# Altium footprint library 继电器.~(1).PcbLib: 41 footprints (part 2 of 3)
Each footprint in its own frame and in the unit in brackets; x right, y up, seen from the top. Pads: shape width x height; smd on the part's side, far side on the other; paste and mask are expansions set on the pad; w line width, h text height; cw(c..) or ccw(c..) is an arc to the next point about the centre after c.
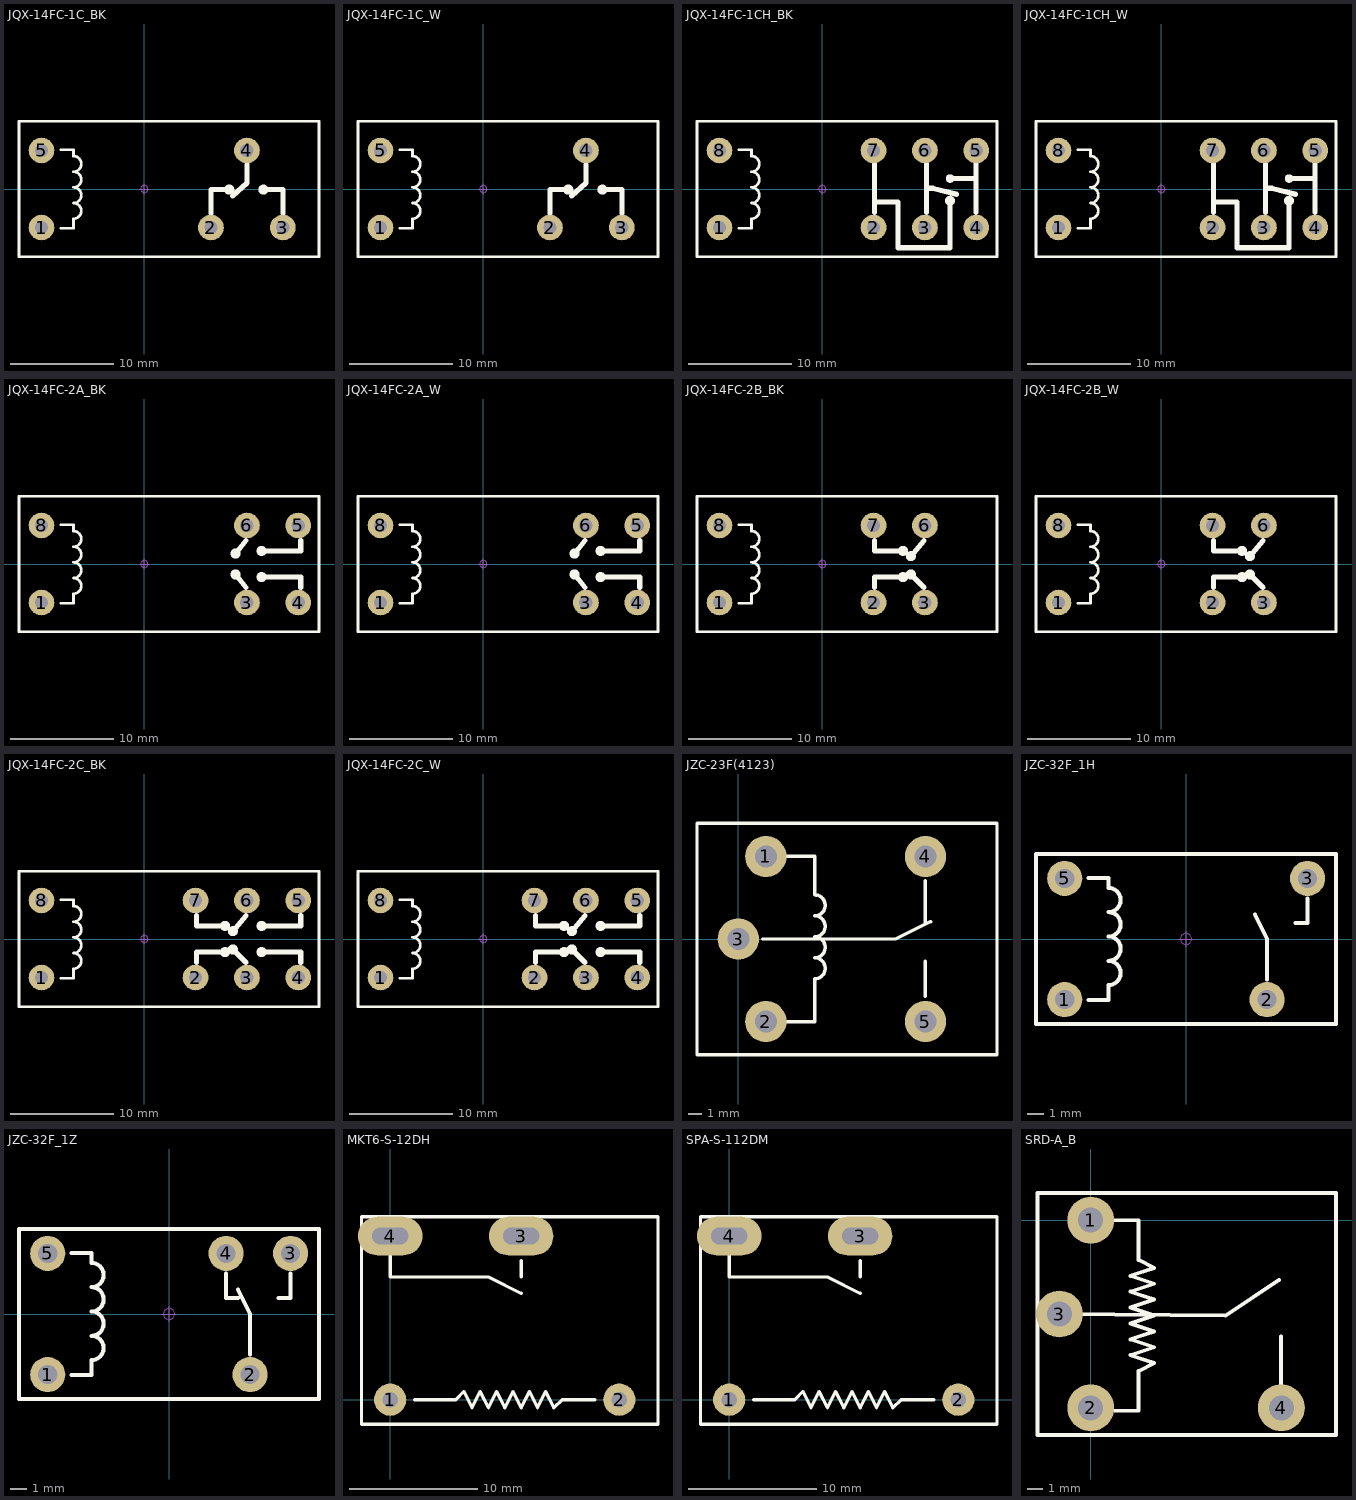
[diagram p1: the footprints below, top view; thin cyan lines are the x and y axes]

## JQX-14FC-1C_BK [mm] "单刀双投，长：29mm，宽：13mm，高：26mm"
pads (5):
  round 2.5 hole 1.3: 1(-10,-3.75) 2(6.5,-3.75) 3(13.5,-3.75) 4(10,3.75) 5(-10,3.75)
Top Overlay:
  circle w0.254: c11.595,-0.06 r0.359
  circle w0.254: c8.278,-0.06 r0.37
  lines w0.25: -12.192,-6.604 17.018,-6.604 17.018,6.604 -12.065,6.604 -12.192,6.604 -12.192,-6.604
  lines w0.254: -8.128,-3.81 -6.89,-3.81 -6.89,-2.89 ccw(c-6.89,-2.128) -6.89,-1.366 ccw(c-6.89,-0.604) -6.89,0.158 ccw(c-6.89,0.92) -6.89,1.682 ccw(c-6.89,2.444) -6.89,3.206 -6.89,3.81 -8.128,3.81
  lines w0.508: 6.5,-2.353 6.5,-0.06 8.278,-0.06 ; 8.603,-0.695 10,0.575 10,2.353 ; 11.595,-0.06 13.5,-0.06 13.5,-2.353
Mechanical 15:
  circle w0.05: c0,0 r0.35
  lines w0.05: -0.5,0 0.5,0 ; 0,-0.5 0,0.5
3D body: height 26.35, standoff -3.65, extent -12.1,-6.5 16.9,6.5

## JQX-14FC-1C_W [mm] "单刀双投，长：29mm，宽：13mm，高：26mm"
pads (5):
  round 2.5 hole 1.3: 1(-10,-3.75) 2(6.5,-3.75) 3(13.5,-3.75) 4(10,3.75) 5(-10,3.75)
Top Overlay:
  circle w0.254: c8.278,-0.06 r0.37
  circle w0.254: c11.595,-0.06 r0.359
  lines w0.25: -12.192,-6.604 -12.192,6.604 -12.065,6.604 17.018,6.604 17.018,-6.604 -12.192,-6.604
  lines w0.254: -8.128,-3.81 -6.89,-3.81 -6.89,-2.89 ccw(c-6.89,-2.128) -6.89,-1.366 ccw(c-6.89,-0.604) -6.89,0.158 ccw(c-6.89,0.92) -6.89,1.682 ccw(c-6.89,2.444) -6.89,3.206 -6.89,3.81 -8.128,3.81
  lines w0.508: 6.5,-2.353 6.5,-0.06 8.278,-0.06 ; 8.603,-0.695 10,0.575 10,2.353 ; 11.595,-0.06 13.5,-0.06 13.5,-2.353
Mechanical 15:
  circle w0.05: c0,0 r0.35
  lines w0.05: -0.5,0 0.5,0 ; 0,-0.5 0,0.5
3D body: height 26.35, standoff -3.65, extent -12.1,-6.5 16.9,6.5

## JQX-14FC-1CH_BK [mm] "单刀双投，长：29mm，宽：13mm，高：26mm"
pads (8):
  round 2.5 hole 1.3: 1(-10,-3.75) 2(5,-3.75) 3(10,-3.75) 4(15,-3.75) 5(15,3.75) 6(10,3.75) 7(5,3.75) 8(-10,3.75)
Top Overlay:
  circle w0.254: c12.446,-1.143 r0.359
  circle w0.254: c12.446,1.016 r0.284
  lines w0.25: -12.192,-6.604 -12.192,6.604 -12.065,6.604 17.018,6.604 17.018,-6.604 -12.192,-6.604
  lines w0.254: -8.128,-3.81 -6.89,-3.81 -6.89,-2.89 ccw(c-6.89,-2.128) -6.89,-1.366 ccw(c-6.89,-0.604) -6.89,0.158 ccw(c-6.89,0.92) -6.89,1.682 ccw(c-6.89,2.444) -6.89,3.206 -6.89,3.81 -8.128,3.81
  lines w0.508: 5.08,-2.286 5.08,2.413 ; 5.08,-1.27 7.366,-1.27 7.366,-5.715 12.446,-5.715 12.446,-2.413 12.446,-1.143 ; 10.16,-2.286 10.16,2.413 ; 10.16,0.064 10.795,0.064 13.081,-0.508 ; 12.446,1.016 14.986,1.016 ; 14.986,-2.286 14.986,2.413
Mechanical 15:
  circle w0.05: c0,0 r0.35
  lines w0.05: -0.5,0 0.5,0 ; 0,-0.5 0,0.5
3D body: height 26.35, standoff -3.65, extent -12.1,-6.5 16.9,6.5

## JQX-14FC-1CH_W [mm] "单刀双投，长：29mm，宽：13mm，高：26mm"
pads (8):
  round 2.5 hole 1.3: 1(-10,-3.75) 2(5,-3.75) 3(10,-3.75) 4(15,-3.75) 5(15,3.75) 6(10,3.75) 7(5,3.75) 8(-10,3.75)
Top Overlay:
  circle w0.254: c12.446,-1.143 r0.359
  circle w0.254: c12.446,1.016 r0.284
  lines w0.25: -12.192,-6.604 -12.192,6.604 -12.065,6.604 17.018,6.604 17.018,-6.604 -12.192,-6.604
  lines w0.254: -8.128,-3.81 -6.89,-3.81 -6.89,-2.89 ccw(c-6.89,-2.128) -6.89,-1.366 ccw(c-6.89,-0.604) -6.89,0.158 ccw(c-6.89,0.92) -6.89,1.682 ccw(c-6.89,2.444) -6.89,3.206 -6.89,3.81 -8.128,3.81
  lines w0.508: 5.08,-2.286 5.08,2.413 ; 5.08,-1.27 7.366,-1.27 7.366,-5.715 12.446,-5.715 12.446,-2.413 12.446,-1.143 ; 10.16,-2.286 10.16,2.413 ; 10.16,0.064 10.795,0.064 13.081,-0.508 ; 12.446,1.016 14.986,1.016 ; 14.986,-2.286 14.986,2.413
Mechanical 15:
  circle w0.05: c0,0 r0.35
  lines w0.05: -0.5,0 0.5,0 ; 0,-0.5 0,0.5
3D body: height 26.35, standoff -3.65, extent -12.1,-6.5 16.9,6.5

## JQX-14FC-2A_BK [mm] "双刀常开，长：29mm，宽：13mm，高：26mm"
pads (6):
  round 2.5 hole 1.3: 1(-10,-3.75) 3(10,-3.75) 4(15,-3.75) 5(15,3.75) 6(10,3.75) 8(-10,3.75)
Top Overlay:
  circle w0.254: c8.89,-1.016 r0.359
  circle w0.254: c8.89,1.016 r0.359
  circle w0.254: c11.43,-1.27 r0.359
  circle w0.254: c11.43,1.27 r0.359
  lines w0.25: -12.192,-6.604 -12.192,6.604 -12.065,6.604 17.018,6.604 17.018,-6.604 -12.192,-6.604
  lines w0.254: -8.128,-3.81 -6.89,-3.81 -6.89,-2.89 ccw(c-6.89,-2.128) -6.89,-1.366 ccw(c-6.89,-0.604) -6.89,0.158 ccw(c-6.89,0.92) -6.89,1.682 ccw(c-6.89,2.444) -6.89,3.206 -6.89,3.81 -8.128,3.81
  lines w0.508: 8.89,-1.016 9.906,-2.286 ; 8.89,1.016 9.906,2.286 ; 11.43,-1.27 15.24,-1.27 15.24,-2.286 ; 11.43,1.27 15.24,1.27 15.24,2.286
Mechanical 15:
  circle w0.05: c0,0 r0.35
  lines w0.05: -0.5,0 0.5,0 ; 0,-0.5 0,0.5
3D body: height 26.35, standoff -3.65, extent -12.1,-6.5 16.9,6.5

## JQX-14FC-2A_W [mm] "双刀常开，长：29mm，宽：13mm，高：26mm"
pads (6):
  round 2.5 hole 1.3: 1(-10,-3.75) 3(10,-3.75) 4(15,-3.75) 5(15,3.75) 6(10,3.75) 8(-10,3.75)
Top Overlay:
  circle w0.254: c8.89,-1.016 r0.359
  circle w0.254: c8.89,1.016 r0.359
  circle w0.254: c11.43,-1.27 r0.359
  circle w0.254: c11.43,1.27 r0.359
  lines w0.25: -12.192,-6.604 -12.192,6.604 -12.065,6.604 17.018,6.604 17.018,-6.604 -12.192,-6.604
  lines w0.254: -8.128,-3.81 -6.89,-3.81 -6.89,-2.89 ccw(c-6.89,-2.128) -6.89,-1.366 ccw(c-6.89,-0.604) -6.89,0.158 ccw(c-6.89,0.92) -6.89,1.682 ccw(c-6.89,2.444) -6.89,3.206 -6.89,3.81 -8.128,3.81
  lines w0.508: 8.89,-1.016 9.906,-2.286 ; 8.89,1.016 9.906,2.286 ; 11.43,-1.27 15.24,-1.27 15.24,-2.286 ; 11.43,1.27 15.24,1.27 15.24,2.286
Mechanical 15:
  circle w0.05: c0,0 r0.35
  lines w0.05: -0.5,0 0.5,0 ; 0,-0.5 0,0.5
3D body: height 26.35, standoff -3.65, extent -12.1,-6.5 16.9,6.5

## JQX-14FC-2B_BK [mm] "双刀常闭，长：29mm，宽：13mm，高：26mm"
pads (6):
  round 2.5 hole 1.3: 1(-10,-3.75) 2(5,-3.75) 3(10,-3.75) 6(10,3.75) 7(5,3.75) 8(-10,3.75)
Top Overlay:
  circle w0.254: c8.636,-1.016 r0.359
  circle w0.254: c8.636,0.762 r0.359
  circle w0.254: c7.874,-1.27 r0.359
  circle w0.254: c7.874,1.27 r0.359
  lines w0.25: -12.192,-6.604 -12.192,6.604 -12.065,6.604 17.018,6.604 17.018,-6.604 -12.192,-6.604
  lines w0.254: -8.128,-3.81 -6.89,-3.81 -6.89,-2.89 ccw(c-6.89,-2.128) -6.89,-1.366 ccw(c-6.89,-0.604) -6.89,0.158 ccw(c-6.89,0.92) -6.89,1.682 ccw(c-6.89,2.444) -6.89,3.206 -6.89,3.81 -8.128,3.81
  lines w0.508: 5.08,-2.286 5.08,-1.27 7.874,-1.27 ; 5.08,2.286 5.08,1.27 7.874,1.27 ; 8.636,-1.016 9.906,-2.286 ; 8.636,0.762 9.906,2.286
Mechanical 15:
  circle w0.05: c0,0 r0.35
  lines w0.05: -0.5,0 0.5,0 ; 0,-0.5 0,0.5
3D body: height 26.35, standoff -3.65, extent -12.1,-6.5 16.9,6.5

## JQX-14FC-2B_W [mm] "双刀常闭，长：29mm，宽：13mm，高：26mm"
pads (6):
  round 2.5 hole 1.3: 1(-10,-3.75) 2(5,-3.75) 3(10,-3.75) 6(10,3.75) 7(5,3.75) 8(-10,3.75)
Top Overlay:
  circle w0.254: c8.636,-1.016 r0.359
  circle w0.254: c8.636,0.762 r0.359
  circle w0.254: c7.874,-1.27 r0.359
  circle w0.254: c7.874,1.27 r0.359
  lines w0.25: -12.192,-6.604 -12.192,6.604 -12.065,6.604 17.018,6.604 17.018,-6.604 -12.192,-6.604
  lines w0.254: -8.128,-3.81 -6.89,-3.81 -6.89,-2.89 ccw(c-6.89,-2.128) -6.89,-1.366 ccw(c-6.89,-0.604) -6.89,0.158 ccw(c-6.89,0.92) -6.89,1.682 ccw(c-6.89,2.444) -6.89,3.206 -6.89,3.81 -8.128,3.81
  lines w0.508: 5.08,-2.286 5.08,-1.27 7.874,-1.27 ; 5.08,2.286 5.08,1.27 7.874,1.27 ; 8.636,-1.016 9.906,-2.286 ; 8.636,0.762 9.906,2.286
Mechanical 15:
  circle w0.05: c0,0 r0.35
  lines w0.05: -0.5,0 0.5,0 ; 0,-0.5 0,0.5
3D body: height 26.35, standoff -3.65, extent -12.1,-6.5 16.9,6.5

## JQX-14FC-2C_BK [mm] "双刀双投，长：29mm，宽：13mm，高：26mm"
pads (8):
  round 2.5 hole 1.3: 1(-10,-3.75) 2(5,-3.75) 3(10,-3.75) 4(15,-3.75) 5(15,3.75) 6(10,3.75) 7(5,3.75) 8(-10,3.75)
Top Overlay:
  circle w0.254: c8.636,-1.016 r0.359
  circle w0.254: c8.636,0.762 r0.359
  circle w0.254: c7.874,-1.27 r0.359
  circle w0.254: c7.874,1.27 r0.359
  circle w0.254: c11.43,-1.27 r0.359
  circle w0.254: c11.43,1.27 r0.359
  lines w0.25: -12.192,-6.604 -12.192,6.604 -12.065,6.604 17.018,6.604 17.018,-6.604 -12.192,-6.604
  lines w0.254: -8.128,-3.81 -6.89,-3.81 -6.89,-2.89 ccw(c-6.89,-2.128) -6.89,-1.366 ccw(c-6.89,-0.604) -6.89,0.158 ccw(c-6.89,0.92) -6.89,1.682 ccw(c-6.89,2.444) -6.89,3.206 -6.89,3.81 -8.128,3.81
  lines w0.508: 5.08,-2.286 5.08,-1.27 7.874,-1.27 ; 5.08,2.286 5.08,1.27 7.874,1.27 ; 8.636,-1.016 9.906,-2.286 ; 8.636,0.762 9.906,2.286 ; 11.43,-1.27 15.24,-1.27 15.24,-2.286 ; 11.43,1.27 15.24,1.27 15.24,2.286
Mechanical 15:
  circle w0.05: c0,0 r0.35
  lines w0.05: -0.5,0 0.5,0 ; 0,-0.5 0,0.5
3D body: height 26.35, standoff -3.65, extent -12.1,-6.5 16.9,6.5

## JQX-14FC-2C_W [mm] "双刀双投，长：29mm，宽：13mm，高：26mm"
pads (8):
  round 2.5 hole 1.3: 1(-10,-3.75) 2(5,-3.75) 3(10,-3.75) 4(15,-3.75) 5(15,3.75) 6(10,3.75) 7(5,3.75) 8(-10,3.75)
Top Overlay:
  circle w0.254: c11.43,1.27 r0.359
  circle w0.254: c11.43,-1.27 r0.359
  circle w0.254: c7.874,1.27 r0.359
  circle w0.254: c7.874,-1.27 r0.359
  circle w0.254: c8.636,0.762 r0.359
  circle w0.254: c8.636,-1.016 r0.359
  lines w0.25: -12.192,-6.604 17.018,-6.604 17.018,6.604 -12.065,6.604 -12.192,6.604 -12.192,-6.604
  lines w0.254: -8.128,-3.81 -6.89,-3.81 -6.89,-2.89 ccw(c-6.89,-2.128) -6.89,-1.366 ccw(c-6.89,-0.604) -6.89,0.158 ccw(c-6.89,0.92) -6.89,1.682 ccw(c-6.89,2.444) -6.89,3.206 -6.89,3.81 -8.128,3.81
  lines w0.508: 5.08,-2.286 5.08,-1.27 7.874,-1.27 ; 5.08,2.286 5.08,1.27 7.874,1.27 ; 8.636,-1.016 9.906,-2.286 ; 8.636,0.762 9.906,2.286 ; 11.43,-1.27 15.24,-1.27 15.24,-2.286 ; 11.43,1.27 15.24,1.27 15.24,2.286
Mechanical 15:
  circle w0.05: c0,0 r0.35
  lines w0.05: -0.5,0 0.5,0 ; 0,-0.5 0,0.5
3D body: height 26.35, standoff -3.65, extent -12.1,-6.5 16.9,6.5

## JZC-23F(4123) [mm] "单刀双投"
pads (5):
  round 3 hole 1.6: 1(2,6) 2(2,-6) 3(0,0) 4(13.6,6) 5(13.6,-6)
Top Overlay:
  lines w0.254: 1.778,0 11.43,0 13.97,1.27 ; 3.524,-6 5.556,-6 5.556,-2.89 ccw(c5.556,-2.128) 5.556,-1.366 ccw(c5.556,-0.604) 5.556,0.158 ccw(c5.556,0.92) 5.556,1.682 ccw(c5.556,2.444) 5.556,3.206 5.556,6 3.524,6 ; 13.6,-4.16 13.6,-1.62 ; 13.6,1.174 13.6,4.222 ; -3,-8.4 -3,8.4 18.8,8.4 18.8,-8.4 -3,-8.4
3D body: height 16.1, standoff -4, extent -3,-8.4 18.8,8.4

## JZC-32F_1H [mm] "单刀常开,长：18.4mm，宽：10.2mm，高：15.3mm"
pads (4):
  round 2.2 hole 1.2: 1(-7.6,-3.8) 2(5.08,-3.8) 3(7.62,3.8) 5(-7.6,3.8)
Top Overlay:
  lines w0.25: 4.318,1.524 5.08,0 5.08,-2.54 ; 6.858,1.016 7.62,1.016 7.62,2.54 ; -9.398,-5.334 9.398,-5.334 9.398,5.334 -9.398,5.334 -9.398,-5.334
  lines w0.254: -6.096,-3.81 -4.858,-3.81 -4.858,-2.89 ccw(c-4.858,-2.128) -4.858,-1.366 ccw(c-4.858,-0.604) -4.858,0.158 ccw(c-4.858,0.92) -4.858,1.682 ccw(c-4.858,2.444) -4.858,3.206 -4.858,3.81 -6.096,3.81
Mechanical 15:
  circle w0.05: c0,0 r0.35
  lines w0.05: -0.5,0 0.5,0 ; 0,-0.5 0,0.5
3D body: height 15.75, standoff -3.55, extent -9.2,-5.1 9.2,5.1

## JZC-32F_1Z [mm] "单刀双投,长：18.4mm，宽：10.2mm，高：15.3mm"
pads (5):
  round 2.2 hole 1.2: 1(-7.6,-3.8) 2(5.08,-3.8) 3(7.62,3.8) 4(3.58,3.8) 5(-7.6,3.8)
Top Overlay:
  lines w0.25: 3.556,2.54 3.556,1.016 4.318,1.016 ; 4.318,1.524 5.08,0 5.08,-2.54 ; 6.858,1.016 7.62,1.016 7.62,2.54 ; -9.398,-5.334 9.398,-5.334 9.398,5.334 -9.398,5.334 -9.398,-5.334
  lines w0.254: -6.096,-3.81 -4.858,-3.81 -4.858,-2.89 ccw(c-4.858,-2.128) -4.858,-1.366 ccw(c-4.858,-0.604) -4.858,0.158 ccw(c-4.858,0.92) -4.858,1.682 ccw(c-4.858,2.444) -4.858,3.206 -4.858,3.81 -6.096,3.81
Mechanical 15:
  circle w0.05: c0,0 r0.35
  lines w0.05: -0.5,0 0.5,0 ; 0,-0.5 0,0.5
3D body: height 15.75, standoff -3.55, extent -9.2,-5.1 9.2,5.1

## MKT6-S-12DH [mm] "单刀单投/常开"
pads (4):
  round 2.5 hole 1.2: 1(0,0) 2(17.78,0)
  oval 5x3 hole 1.3 slot 2.8 at 0 deg: 3(10.16,12.7) 4(0,12.7)
Top Overlay:
  lines w0.254: 0,11.43 0,9.525 6.985,9.525 7.62,9.525 10.16,8.255 ; 1.905,0 5.08,0 5.715,0.635 6.35,-0.635 6.985,0.635 7.62,-0.635 8.255,0.635 8.89,-0.635 9.525,0.635 10.16,-0.635 10.795,0.635 11.43,-0.635 12.065,0.635 12.7,-0.635 13.335,0 15.875,0 ; 10.16,9.525 10.16,10.795 ; -2.22,-1.9 -2.22,14.2 20.78,14.2 20.78,-1.9 -2.22,-1.9
3D body: height 10.2, standoff -3.9, extent -2.24,-1.9 20.76,14.2

## SPA-S-112DM [mm] "单刀单投/常开"
pads (4):
  round 2.5 hole 1.2: 1(0,0) 2(17.78,0)
  oval 5x3 hole 1.3 slot 2.8 at 0 deg: 3(10.16,12.7) 4(0,12.7)
Top Overlay:
  lines w0.254: 0,11.43 0,9.525 6.985,9.525 7.62,9.525 10.16,8.255 ; 1.905,0 5.08,0 5.715,0.635 6.35,-0.635 6.985,0.635 7.62,-0.635 8.255,0.635 8.89,-0.635 9.525,0.635 10.16,-0.635 10.795,0.635 11.43,-0.635 12.065,0.635 12.7,-0.635 13.335,0 15.875,0 ; 10.16,9.525 10.16,10.795 ; -2.22,-1.9 -2.22,14.2 20.78,14.2 20.78,-1.9 -2.22,-1.9
3D body: height 10.2, standoff -3.9, extent -2.24,-1.9 20.76,14.2

## SRD-A_B [mm] "单刀单投/常开"
pads (4):
  round 3 hole 1.6: 1(0,0) 2(0,-12) 3(-2,-6) 4(12.2,-12)
Top Overlay:
  lines w0.254: -2,-6 8.636,-6.096 12.065,-3.81 ; 1.524,-12.192 3.048,-12.192 3.048,-10.668 3.048,-9.652 4.064,-9.144 2.54,-8.636 4.064,-8.128 2.54,-7.62 4.064,-7.112 2.54,-6.604 4.064,-6.096 2.54,-5.588 4.064,-5.08 2.54,-4.572 4.064,-4.064 2.54,-3.556 4.064,-3.048 3.048,-2.54 3.048,0 1.524,0 ; 12.192,-10.668 12.192,-8.636 ; 12.192,-9.144 12.192,-7.429 ; -3.4,-13.75 -3.4,1.75 15.7,1.75 15.7,-13.75 -3.4,-13.75
3D body: height 15.6, standoff -3.4, extent -3.4,-13.75 15.7,1.75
